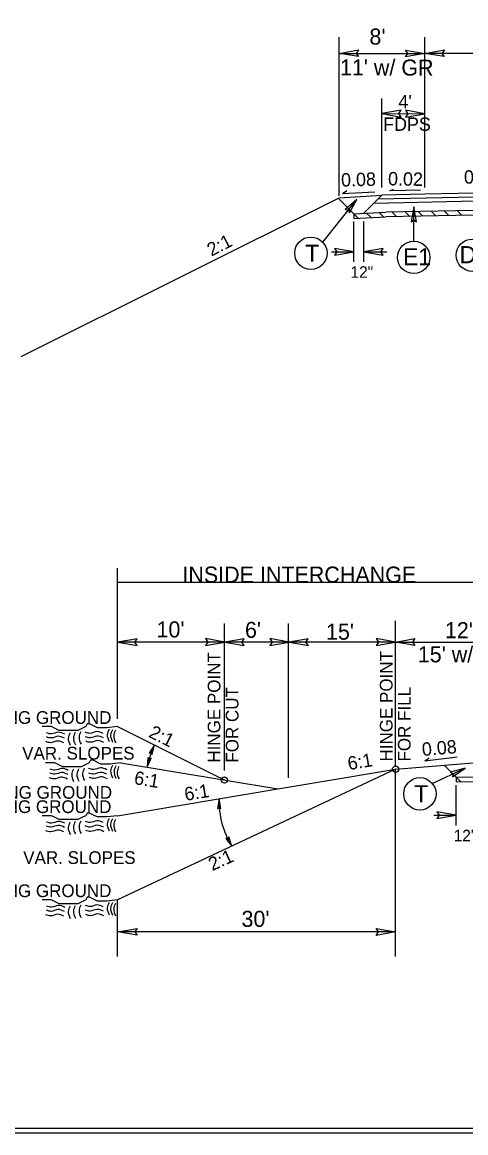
# Model space of a CAD drawing. Extents: x 573813 to 575363, y -54752 to -53123.
# Drawn here: x 574787 to 574834.1, y -53558.6 to -53440.6 of the extents above; entities that cross this region are included whole.
import ezdxf

# ---------------------------------------------------------------- set-up
doc = ezdxf.new("R2010")
doc.units = 0
for name, color, linetype in [('Old_Level_1', 7, 'Continuous'), ('Old_Level_11', 7, 'Continuous'), ('Old_Level_2', 7, 'Continuous'), ('Old_Level_3', 7, 'Continuous'), ('Prop Pavement Schedule Description CELL', 7, 'Continuous'), ('Sheet Plot Border Inside CELL', 7, 'Continuous'), ('Sheet Typical CELL', 7, 'Continuous'), ('Typical ID Circle CELL', 7, 'Continuous'), ('Typical Terminator CELL', 7, 'Continuous'), ('Typical Text ID Circle CELL', 7, 'Continuous')]:
    doc.layers.add(name, color=color, linetype=linetype)

msp = doc.modelspace()

# ---------------------------------------------------------------- linework, layer by layer
at = {"layer": 'Old_Level_1'}
for p, q in [((574826.03, -53458.54), (574826.41, -53458.35)), ((574829.3, -53458.47), (574826.03, -53458.54)), ((574853.33, -53458.42), (574829.74, -53458.91)), ((574786.87, -53476.15), (574820.64, -53459.27)), ((574820.54, -53459.32), (574822.2, -53460.97)), ((574820.64, -53459.27), (574825.19, -53459)), ((574825.19, -53459), (574823.27, -53460.92)), ((574853.33, -53459.27), (574824.32, -53459.88)), ((574853.33, -53458.83), (574824.77, -53459.42)), ((574829.74, -53458.91), (574825.19, -53459)), ((574822.2, -53460.97), (574825.61, -53460.81)), ((574822.2, -53460.97), (574822.2, -53461.47)), ((574822.2, -53460.97), (574822.67, -53461.45)), ((574823.55, -53460.91), (574824.03, -53461.39)), ((574824.9, -53460.85), (574825.38, -53461.32)), ((574853.33, -53460.24), (574825.61, -53460.81)), ((574853.33, -53460.74), (574825.62, -53461.31)), ((574826.27, -53460.8), (574826.76, -53461.29)), ((574827.65, -53460.77), (574828.14, -53461.26)), ((574829.04, -53460.74), (574829.53, -53461.23)), ((574830.42, -53460.71), (574830.91, -53461.2)), ((574831.81, -53460.68), (574832.3, -53461.17)), ((574833.2, -53460.66), (574833.69, -53461.15)), ((574822.2, -53461.47), (574825.62, -53461.31)), ((574797.08, -53515.43), (574807.37, -53520.58)), ((574797.44, -53519.28), (574814.12, -53522.06)), ((574826.64, -53519.97), (574835.74, -53519.22)), ((574831.81, -53519.54), (574833.08, -53520.82)), ((574826.64, -53519.97), (574797.08, -53533.83)), ((574807.37, -53520.58), (574808.45, -53521.11)), ((574818.59, -53521.31), (574826.64, -53519.97)), ((574833.08, -53520.82), (574840.28, -53520.67)), ((574833.08, -53520.82), (574833.08, -53521.32)), ((574833.08, -53520.82), (574833.57, -53521.31)), ((574797.08, -53524.9), (574814.12, -53522.06)), ((574814.12, -53522.06), (574818.59, -53521.31)), ((574833.08, -53521.32), (574840.29, -53521.17))]:
    msp.add_line(p, q, dxfattribs=at)
for points in [[(574797.08, -53515.43), (574795.96, -53515.57), (574795.68, -53515.57), (574795.26, -53515.57), (574794.98, -53515.57), (574794.7, -53515.43), (574794.42, -53515.29), (574794.14, -53515.15), (574793.86, -53515.15), (574793.72, -53515.43), (574793.44, -53515.57), (574793.16, -53515.71), (574792.88, -53515.85), (574792.6, -53515.85), (574792.32, -53515.85), (574792.04, -53515.85), (574791.76, -53515.85), (574791.48, -53515.85), (574791.19, -53515.85), (574790.91, -53515.85), (574790.63, -53515.71), (574790.35, -53515.57), (574790.07, -53515.43), (574789.65, -53515.43), (574789.37, -53515.43), (574789.09, -53515.43)], [(574797.44, -53519.28), (574796.32, -53519.42), (574796.04, -53519.42), (574795.62, -53519.42), (574795.34, -53519.42), (574795.06, -53519.28), (574794.78, -53519.14), (574794.5, -53519), (574794.22, -53519), (574794.08, -53519.28), (574793.8, -53519.42), (574793.52, -53519.56), (574793.24, -53519.7), (574792.96, -53519.7), (574792.68, -53519.7), (574792.4, -53519.7), (574792.12, -53519.7), (574791.84, -53519.7), (574791.56, -53519.7), (574791.28, -53519.7), (574791, -53519.56), (574790.72, -53519.42), (574790.44, -53519.28), (574790.02, -53519.28), (574789.74, -53519.28), (574789.46, -53519.28)], [(574797.08, -53524.9), (574795.96, -53525.04), (574795.68, -53525.04), (574795.26, -53525.04), (574794.98, -53525.04), (574794.7, -53524.9), (574794.42, -53524.76), (574794.14, -53524.62), (574793.86, -53524.62), (574793.72, -53524.9), (574793.44, -53525.04), (574793.16, -53525.18), (574792.87, -53525.32), (574792.59, -53525.32), (574792.31, -53525.32), (574792.03, -53525.32), (574791.75, -53525.32), (574791.47, -53525.32), (574791.19, -53525.32), (574790.91, -53525.32), (574790.63, -53525.18), (574790.35, -53525.04), (574790.07, -53524.9), (574789.65, -53524.9), (574789.37, -53524.9), (574789.09, -53524.9)], [(574797.08, -53533.83), (574795.96, -53533.97), (574795.68, -53533.97), (574795.26, -53533.97), (574794.98, -53533.97), (574794.7, -53533.83), (574794.42, -53533.69), (574794.14, -53533.55), (574793.86, -53533.55), (574793.72, -53533.83), (574793.44, -53533.97), (574793.16, -53534.11), (574792.87, -53534.25), (574792.59, -53534.25), (574792.31, -53534.25), (574792.03, -53534.25), (574791.75, -53534.25), (574791.47, -53534.25), (574791.19, -53534.25), (574790.91, -53534.25), (574790.63, -53534.11), (574790.35, -53533.97), (574790.07, -53533.83), (574789.65, -53533.83), (574789.37, -53533.83), (574789.09, -53533.83)]]:
    msp.add_lwpolyline(points, dxfattribs=at)
for centre in [(574826.64, -53519.97), (574826.64, -53519.97), (574808.45, -53521.11)]:
    msp.add_circle(centre, 0.338, dxfattribs=at)
for centre, start, end in [((574808.93, -53521.25), 153.9334, 170.1878), ((574816.69, -53523.44), 177.8236, 212.181)]:
    msp.add_arc(centre, 8.8, start, end, dxfattribs=at)
at = {"layer": 'Old_Level_11'}
for p, q in [((574820.64, -53459.08), (574820.64, -53442.21)), ((574829.74, -53458.18), (574829.74, -53442.21)), ((574820.64, -53443.94), (574829.74, -53443.94)), ((574843.41, -53443.94), (574829.76, -53443.94)), ((574825.19, -53458.18), (574825.19, -53448.73)), ((574825.19, -53450.34), (574829.74, -53450.35)), ((574822.2, -53466.09), (574822.2, -53461.8)), ((574823.27, -53466.09), (574823.27, -53461.78)), ((574819.84, -53465.01), (574822.2, -53465.01)), ((574823.27, -53465.01), (574825.71, -53465.02)), ((574797.08, -53514.61), (574797.08, -53498.6)), ((574840.28, -53500.15), (574797.08, -53500.15)), ((574808.45, -53520.11), (574808.45, -53504.48)), ((574815.27, -53520.88), (574815.27, -53504.48)), ((574826.64, -53519.57), (574826.64, -53504.21)), ((574808.5, -53506.47), (574797.13, -53506.47)), ((574815.32, -53506.47), (574808.5, -53506.47)), ((574826.69, -53506.46), (574815.32, -53506.47)), ((574826.64, -53506.46), (574840.28, -53506.46)), ((574826.64, -53539.86), (574826.64, -53519.97)), ((574833.08, -53525.94), (574833.08, -53521.65)), ((574830.72, -53524.85), (574833.08, -53524.86)), ((574797.08, -53539.86), (574797.08, -53533.83)), ((574826.64, -53537.25), (574797.13, -53537.25))]:
    msp.add_line(p, q, dxfattribs=at)
for points in [[(574822.69, -53444.29), (574820.64, -53443.94), (574822.7, -53443.58), (574822.44, -53443.94)], [(574827.69, -53443.59), (574829.74, -53443.94), (574827.68, -53444.31), (574827.94, -53443.94)], [(574831.81, -53444.29), (574829.76, -53443.94), (574831.82, -53443.58), (574831.56, -53443.94)], [(574827.24, -53449.99), (574825.19, -53450.34), (574827.25, -53450.7), (574826.99, -53450.34)], [(574827.69, -53450.7), (574829.74, -53450.35), (574827.68, -53449.98), (574827.94, -53450.35)], [(574820.15, -53465.36), (574822.2, -53465.01), (574820.14, -53464.65), (574820.4, -53465.01)], [(574825.32, -53464.66), (574823.27, -53465.01), (574825.33, -53465.38), (574825.07, -53465.01)], [(574799.18, -53506.11), (574797.13, -53506.47), (574799.19, -53506.83), (574798.93, -53506.47)], [(574806.46, -53506.82), (574808.5, -53506.47), (574806.44, -53506.1), (574806.71, -53506.47)], [(574810.55, -53506.11), (574808.5, -53506.47), (574810.56, -53506.83), (574810.3, -53506.47)], [(574813.28, -53506.82), (574815.32, -53506.47), (574813.27, -53506.1), (574813.53, -53506.47)], [(574817.37, -53506.11), (574815.32, -53506.47), (574817.38, -53506.83), (574817.12, -53506.47)], [(574824.59, -53506.82), (574826.64, -53506.46), (574824.58, -53506.1), (574824.84, -53506.46)], [(574828.69, -53506.82), (574826.64, -53506.46), (574828.7, -53506.1), (574828.44, -53506.46)], [(574800.78, -53518.39), (574801.03, -53517.38), (574800.45, -53518.26), (574800.67, -53518.21)], [(574800.32, -53518.71), (574800.26, -53519.75), (574800.67, -53518.79), (574800.46, -53518.87)], [(574808.08, -53524.13), (574807.9, -53523.11), (574807.73, -53524.14), (574807.91, -53524)], [(574831.03, -53525.21), (574833.08, -53524.86), (574831.02, -53524.49), (574831.28, -53524.86)], [(574808.61, -53527.31), (574809.25, -53528.13), (574808.92, -53527.13), (574808.82, -53527.34)], [(574799.18, -53537.6), (574797.13, -53537.25), (574799.19, -53536.88), (574798.93, -53537.25)], [(574824.59, -53536.89), (574826.64, -53537.25), (574824.58, -53537.61), (574824.84, -53537.25)]]:
    msp.add_lwpolyline(points, close=True, dxfattribs=at)
at = {"layer": 'Old_Level_2'}
for p, q in [((574821, -53458.81), (574821.46, -53458.51)), ((574821, -53458.81), (574824.43, -53458.64)), ((574829.76, -53519.08), (574833.17, -53518.66)), ((574829.76, -53519.08), (574830.19, -53518.76))]:
    msp.add_line(p, q, dxfattribs=at)
for points in [[(574791.49, -53516.24), (574790.8, -53516.04), (574790.08, -53516.22), (574789.56, -53516.11)], [(574791.49, -53516.24), (574790.8, -53516.04), (574790.08, -53516.22), (574789.56, -53516.11)], [(574792.05, -53516.1), (574791.86, -53516.67), (574792.07, -53517.42)], [(574792.05, -53516.1), (574791.86, -53516.67), (574792.07, -53517.42)], [(574792.61, -53516.06), (574792.41, -53516.62), (574792.62, -53517.37)], [(574792.61, -53516.06), (574792.41, -53516.62), (574792.62, -53517.37)], [(574793.2, -53516.01), (574793.01, -53516.57), (574793.22, -53517.32)], [(574793.2, -53516.01), (574793.01, -53516.57), (574793.22, -53517.32)], [(574795.59, -53516.17), (574794.91, -53515.97), (574794.19, -53516.16), (574793.67, -53516.04)], [(574795.59, -53516.17), (574794.91, -53515.97), (574794.19, -53516.16), (574793.67, -53516.04)], [(574796.2, -53515.73), (574796, -53516.3), (574796.21, -53517.04)], [(574796.2, -53515.73), (574796, -53516.3), (574796.21, -53517.04)], [(574796.55, -53515.77), (574796.36, -53516.33), (574796.57, -53517.08)], [(574796.55, -53515.77), (574796.36, -53516.33), (574796.57, -53517.08)], [(574796.88, -53515.83), (574796.69, -53516.4), (574796.9, -53517.15)], [(574796.88, -53515.83), (574796.69, -53516.4), (574796.9, -53517.15)], [(574791.4, -53517.16), (574790.72, -53516.97), (574789.99, -53517.15), (574789.47, -53517.03)], [(574791.4, -53517.16), (574790.72, -53516.97), (574789.99, -53517.15), (574789.47, -53517.03)], [(574791.47, -53516.66), (574790.78, -53516.47), (574790.07, -53516.65), (574789.54, -53516.54)], [(574791.47, -53516.66), (574790.78, -53516.47), (574790.07, -53516.65), (574789.54, -53516.54)], [(574795.6, -53516.65), (574794.91, -53516.45), (574794.19, -53516.64), (574793.67, -53516.52)], [(574795.6, -53516.65), (574794.91, -53516.45), (574794.19, -53516.64), (574793.67, -53516.52)], [(574795.65, -53517.13), (574794.97, -53516.93), (574794.24, -53517.11), (574793.72, -53517)], [(574795.65, -53517.13), (574794.97, -53516.93), (574794.24, -53517.11), (574793.72, -53517)], [(574791.85, -53520.09), (574791.17, -53519.89), (574790.45, -53520.08), (574789.93, -53519.96)], [(574791.85, -53520.09), (574791.17, -53519.89), (574790.45, -53520.08), (574789.93, -53519.96)], [(574792.42, -53519.96), (574792.23, -53520.52), (574792.43, -53521.27)], [(574792.42, -53519.96), (574792.23, -53520.52), (574792.43, -53521.27)], [(574792.97, -53519.91), (574792.78, -53520.47), (574792.98, -53521.22)], [(574792.97, -53519.91), (574792.78, -53520.47), (574792.98, -53521.22)], [(574793.57, -53519.86), (574793.38, -53520.42), (574793.58, -53521.17)], [(574793.57, -53519.86), (574793.38, -53520.42), (574793.58, -53521.17)], [(574795.96, -53520.02), (574795.28, -53519.82), (574794.55, -53520.01), (574794.03, -53519.89)], [(574795.96, -53520.02), (574795.28, -53519.82), (574794.55, -53520.01), (574794.03, -53519.89)], [(574796.56, -53519.58), (574796.37, -53520.15), (574796.58, -53520.89)], [(574796.56, -53519.58), (574796.37, -53520.15), (574796.58, -53520.89)], [(574796.92, -53519.62), (574796.73, -53520.18), (574796.93, -53520.93)], [(574796.92, -53519.62), (574796.73, -53520.18), (574796.93, -53520.93)], [(574797.25, -53519.68), (574797.06, -53520.25), (574797.26, -53521)], [(574797.25, -53519.68), (574797.06, -53520.25), (574797.26, -53521)], [(574791.77, -53521.01), (574791.08, -53520.82), (574790.36, -53521), (574789.84, -53520.88)], [(574791.77, -53521.01), (574791.08, -53520.82), (574790.36, -53521), (574789.84, -53520.88)], [(574791.84, -53520.52), (574791.15, -53520.32), (574790.43, -53520.5), (574789.91, -53520.39)], [(574791.84, -53520.52), (574791.15, -53520.32), (574790.43, -53520.5), (574789.91, -53520.39)], [(574795.96, -53520.5), (574795.28, -53520.3), (574794.56, -53520.49), (574794.04, -53520.37)], [(574795.96, -53520.5), (574795.28, -53520.3), (574794.56, -53520.49), (574794.04, -53520.37)], [(574796.02, -53520.98), (574795.33, -53520.78), (574794.61, -53520.96), (574794.09, -53520.85)], [(574796.02, -53520.98), (574795.33, -53520.78), (574794.61, -53520.96), (574794.09, -53520.85)], [(574791.49, -53525.71), (574790.8, -53525.51), (574790.08, -53525.7), (574789.56, -53525.58)], [(574791.49, -53525.71), (574790.8, -53525.51), (574790.08, -53525.7), (574789.56, -53525.58)], [(574792.05, -53525.58), (574791.86, -53526.14), (574792.07, -53526.89)], [(574792.05, -53525.58), (574791.86, -53526.14), (574792.07, -53526.89)], [(574792.61, -53525.53), (574792.41, -53526.09), (574792.62, -53526.84)], [(574792.61, -53525.53), (574792.41, -53526.09), (574792.62, -53526.84)], [(574793.2, -53525.48), (574793.01, -53526.04), (574793.22, -53526.79)], [(574793.2, -53525.48), (574793.01, -53526.04), (574793.22, -53526.79)], [(574795.59, -53525.64), (574794.91, -53525.44), (574794.19, -53525.63), (574793.67, -53525.51)], [(574795.59, -53525.64), (574794.91, -53525.44), (574794.19, -53525.63), (574793.67, -53525.51)], [(574796.2, -53525.2), (574796, -53525.77), (574796.21, -53526.51)], [(574796.2, -53525.2), (574796, -53525.77), (574796.21, -53526.51)], [(574796.55, -53525.24), (574796.36, -53525.8), (574796.57, -53526.55)], [(574796.55, -53525.24), (574796.36, -53525.8), (574796.57, -53526.55)], [(574796.88, -53525.3), (574796.69, -53525.87), (574796.9, -53526.62)], [(574796.88, -53525.3), (574796.69, -53525.87), (574796.9, -53526.62)], [(574791.4, -53526.63), (574790.72, -53526.44), (574789.99, -53526.62), (574789.47, -53526.5)], [(574791.4, -53526.63), (574790.72, -53526.44), (574789.99, -53526.62), (574789.47, -53526.5)], [(574791.47, -53526.14), (574790.78, -53525.94), (574790.06, -53526.12), (574789.54, -53526.01)], [(574791.47, -53526.14), (574790.78, -53525.94), (574790.06, -53526.12), (574789.54, -53526.01)], [(574795.6, -53526.12), (574794.91, -53525.92), (574794.19, -53526.11), (574793.67, -53525.99)], [(574795.6, -53526.12), (574794.91, -53525.92), (574794.19, -53526.11), (574793.67, -53525.99)], [(574795.65, -53526.6), (574794.97, -53526.4), (574794.24, -53526.59), (574793.72, -53526.47)], [(574795.65, -53526.6), (574794.97, -53526.4), (574794.24, -53526.59), (574793.72, -53526.47)], [(574791.47, -53535.07), (574790.78, -53534.87), (574790.06, -53535.06), (574789.54, -53534.94)], [(574791.47, -53535.07), (574790.78, -53534.87), (574790.06, -53535.06), (574789.54, -53534.94)], [(574791.49, -53534.64), (574790.8, -53534.44), (574790.08, -53534.63), (574789.56, -53534.51)], [(574791.49, -53534.64), (574790.8, -53534.44), (574790.08, -53534.63), (574789.56, -53534.51)], [(574792.05, -53534.51), (574791.86, -53535.07), (574792.07, -53535.82)], [(574792.05, -53534.51), (574791.86, -53535.07), (574792.07, -53535.82)], [(574792.61, -53534.46), (574792.41, -53535.02), (574792.62, -53535.77)], [(574792.61, -53534.46), (574792.41, -53535.02), (574792.62, -53535.77)], [(574793.2, -53534.41), (574793.01, -53534.97), (574793.21, -53535.72)], [(574793.2, -53534.41), (574793.01, -53534.97), (574793.21, -53535.72)], [(574795.59, -53534.57), (574794.91, -53534.38), (574794.19, -53534.56), (574793.67, -53534.44)], [(574795.59, -53534.57), (574794.91, -53534.38), (574794.19, -53534.56), (574793.67, -53534.44)], [(574795.6, -53535.05), (574794.91, -53534.85), (574794.19, -53535.04), (574793.67, -53534.92)], [(574795.6, -53535.05), (574794.91, -53534.85), (574794.19, -53535.04), (574793.67, -53534.92)], [(574796.2, -53534.13), (574796, -53534.7), (574796.21, -53535.44)], [(574796.2, -53534.13), (574796, -53534.7), (574796.21, -53535.44)], [(574796.55, -53534.17), (574796.36, -53534.73), (574796.57, -53535.48)], [(574796.55, -53534.17), (574796.36, -53534.73), (574796.57, -53535.48)], [(574796.88, -53534.23), (574796.69, -53534.8), (574796.9, -53535.55)], [(574796.88, -53534.23), (574796.69, -53534.8), (574796.9, -53535.55)], [(574791.4, -53535.56), (574790.72, -53535.37), (574789.99, -53535.55), (574789.47, -53535.43)], [(574791.4, -53535.56), (574790.72, -53535.37), (574789.99, -53535.55), (574789.47, -53535.43)], [(574795.65, -53535.53), (574794.97, -53535.34), (574794.24, -53535.52), (574793.72, -53535.4)], [(574795.65, -53535.53), (574794.97, -53535.34), (574794.24, -53535.52), (574793.72, -53535.4)]]:
    msp.add_spline(points, degree=3, dxfattribs=at)
at = {"layer": 'Sheet Plot Border Inside CELL'}
msp.add_lwpolyline([(575005.81, -53347.44), (574672.33, -53347.44), (574672.33, -53558.58), (575005.81, -53558.58)], close=True, dxfattribs=at)
at = {"layer": 'Sheet Typical CELL'}
msp.add_lwpolyline([(575003.31, -53347.95), (574703.15, -53347.95), (574703.15, -53558.07), (575003.31, -53558.07)], close=True, dxfattribs=at)
at = {"layer": 'Typical ID Circle CELL'}
for p, q in [((574818.9, -53464), (574822.51, -53459.47)), ((574828.57, -53463.89), (574828.57, -53460.23)), ((574830.53, -53521.47), (574834.03, -53519.85))]:
    msp.add_line(p, q, dxfattribs=at)
for centre in [(574817.64, -53465.17), (574828.57, -53465.61), (574834.8, -53465.38), (574829.22, -53522.58)]:
    msp.add_circle(centre, 1.72, dxfattribs=at)
at = {"layer": 'Typical Terminator CELL'}
for points in [[(574821.73, -53460.88), (574822.51, -53459.47), (574821.29, -53460.54), (574821.64, -53460.56)], [(574828.85, -53461.82), (574828.57, -53460.23), (574828.29, -53461.83), (574828.57, -53461.62)], [(574832.7, -53520.77), (574834.03, -53519.85), (574832.46, -53520.27), (574832.76, -53520.44)]]:
    msp.add_lwpolyline(points, close=True, dxfattribs=at)

# ---------------------------------------------------------------- texts
at = {"layer": 'Old_Level_1'}
for s, height, rotation, p in [('FDPS', 1.421, 359.9999, (574825.32, -53452.17)), ('0.08', 1.421, 1.6633, (574820.87, -53458.1)), ('0.02', 1.421, 1.1919, (574833.92, -53457.79)), ('2:1', 1.421, 27.0855, (574807.07, -53465.54)), ('HINGE POINT', 1.3502, 90, (574808.03, -53519.27)), ('HINGE POINT', 1.3502, 90, (574826.32, -53519.15)), ('FOR CUT ', 1.35, 90, (574809.95, -53519.27)), ('FOR FILL', 1.35, 90, (574828.24, -53519.15)), ('EXISTING GROUND', 1.3502, 0, (574779.5, -53515.15)), ('2:1', 1.421, 333.435, (574800.31, -53516.5)), ('VAR. SLOPES', 1.3502, 0, (574786.97, -53518.94)), ('6:1', 1.421, 9.4624, (574821.67, -53520.07)), ('6:1', 1.421, 350.5376, (574798.79, -53521.54)), ('EXISTING GROUND', 1.3502, 0, (574779.57, -53523.1)), ('6:1', 1.421, 9.1472, (574804.32, -53523.33)), ('EXISTING GROUND', 1.3502, 0, (574779.5, -53524.62)), ('VAR. SLOPES', 1.3502, 0, (574787.08, -53530.03)), ('2:1', 1.421, 24.2424, (574807.16, -53530.8)), ('EXISTING GROUND', 1.3502, 0, (574779.5, -53533.55))]:
    msp.add_text(s, height=height, rotation=rotation, dxfattribs=at).set_placement(p)
at = {"layer": 'Old_Level_11'}
for s, height, rotation, p in [('INSIDE INTERCHANGE', 1.7055, 0, (574803.99, -53500.15)), ("10'", 1.705, 0, (574801.24, -53505.97)), ("6'", 1.705, 0, (574810.64, -53506.02)), ("15'", 1.705, 0, (574819.25, -53506.21)), ("30'", 1.705, 360, (574810.27, -53536.71))]:
    msp.add_text(s, height=height, rotation=rotation, dxfattribs=at).set_placement(p)
at = {"layer": 'Old_Level_3'}
for s, height, rotation, p in [("8'", 1.705, 359.8329, (574823.86, -53443.01)), ("11' w/ GR", 1.705, 359.8329, (574820.73, -53446.28)), ("4'", 1.421, 359.8329, (574826.94, -53449.77)), ('0.02', 1.421, 358.8543, (574825.83, -53457.95)), ("12'", 1.705, 359.8329, (574831.88, -53506.05)), ("15' w/ GR", 1.705, 359.8329, (574829, -53508.61)), ('0.08', 1.421, 4.8822, (574829.5, -53518.57))]:
    msp.add_text(s, height=height, rotation=rotation, dxfattribs=at).set_placement(p)
at = {"layer": 'Prop Pavement Schedule Description CELL'}
for s, height, p in [('T', 1.82, (574817.04, -53466.08)), ('D1', 1.819, (574833.44, -53466.23)), ('E1', 1.819, (574827.43, -53466.45)), ('T', 1.82, (574828.62, -53523.49))]:
    msp.add_text(s, height=height, rotation=360, dxfattribs=at).set_placement(p)
at = {"layer": 'Typical Text ID Circle CELL'}
for p in [(574821.85, -53467.78), (574832.81, -53527.63)]:
    msp.add_text('12"', height=1.23, dxfattribs=at).set_placement(p)

doc.saveas('drawing.dxf')
